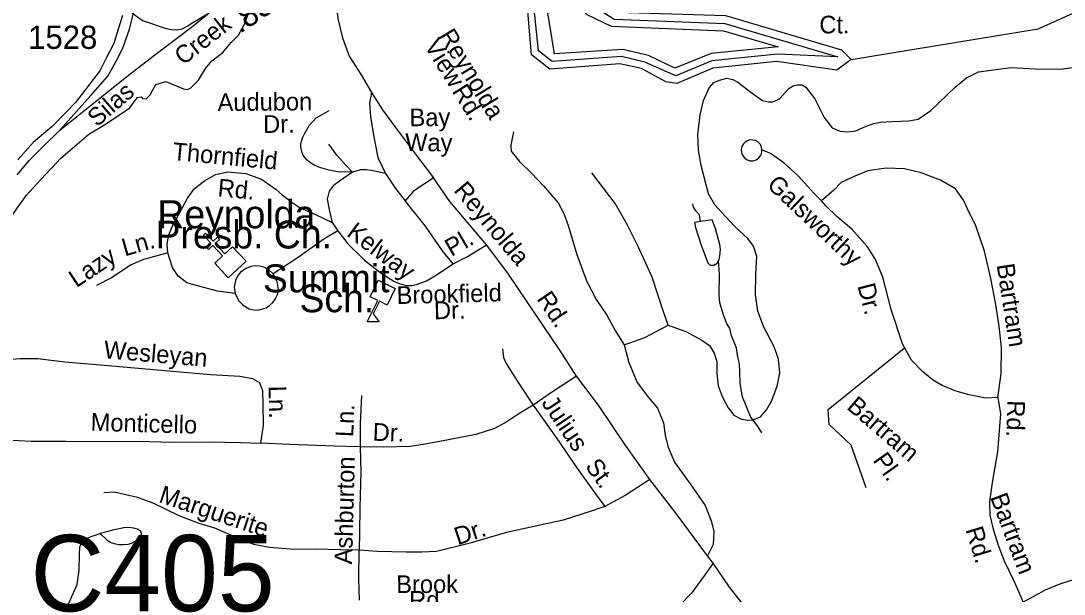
# Model space of a CAD drawing. Extents: x 1547597 to 1699558, y 810033 to 920809.
# Drawn here: x 1618156 to 1623759, y 864801 to 867878 of the extents above; entities that cross this region are included whole.
import ezdxf

# ---------------------------------------------------------------- set-up
doc = ezdxf.new("R2010")
doc.units = 0
for name, color, linetype in [('Exist Cultural Church CELL', 7, 'Continuous'), ('Exist Cultural Church Label', 7, 'Continuous'), ('Exist Cultural Educational Facility High CELL', 7, 'Continuous'), ('Exist Cultural Educational Facility High Label', 7, 'Continuous'), ('Exist Hydrographic Buffer Line', 7, 'Continuous'), ('Exist Hydrographic Creek Single Shore', 7, 'Continuous'), ('Exist Hydrographic Lake Shore', 7, 'Continuous'), ('Exist Hydrographic Misc Water Feature', 7, 'Continuous'), ('Exist Road Non-System Type 51', 7, 'Continuous'), ('Exist Road Non-System Type 51 Label', 7, 'Continuous'), ('Exist Road Primary Interstate Ramp 1 Lane Attributed', 7, 'Continuous'), ('Exist Road Primary NC Service Mileage Hundredths English Label', 7, 'Continuous'), ('Exist Road Primary NC UnDivided 4 Lane Attributed', 7, 'Continuous'), ('Exist Road Secondary Structure Culvert Number Label', 7, 'Continuous'), ('Exist Road Secondary Type 51 Divided Attributed', 7, 'Continuous'), ('Exist Road Secondary Type 51 Number Label', 7, 'Continuous')]:
    doc.layers.add(name, color=color, linetype=linetype)

msp = doc.modelspace()

# ---------------------------------------------------------------- linework, layer by layer
at = {"layer": 'Exist Cultural Church CELL'}
msp.add_lwpolyline([(1619197, 866577.5), (1619238.9, 866616.1), (1619187.4, 866672.2), (1619163.8, 866650.6), (1619153, 866662.3), (1619176.6, 866684), (1619135.9, 866728.3), (1619147.7, 866739.1), (1619188.4, 866694.8), (1619212, 866716.4), (1619222.8, 866704.7), (1619199.2, 866683), (1619250.7, 866626.9), (1619293.2, 866665.8), (1619365.2, 866587.4), (1619268.9, 866499.1)], close=True, dxfattribs=at)
at = {"layer": 'Exist Cultural Educational Facility High CELL'}
msp.add_lwpolyline([(1620165.6, 866440.8), (1620122.6, 866352.8), (1620081.2, 866373), (1620048.3, 866305.5), (1620080, 866263.1), (1620016.3, 866261.7), (1620072.6, 866377.2), (1620031.2, 866397.4), (1620074.2, 866485.4)], close=True, dxfattribs=at)
at = {"layer": 'Exist Hydrographic Buffer Line'}
for points in [[(1620900, 868064.4), (1621049.8, 868125.6), (1621176.8, 868246.5), (1621255.4, 868271.7), (1621206.7, 868118.1), (1621203.8, 867975), (1621342.4, 867886.6), (1621936.5, 867865), (1622544.4, 867686), (1622220.4, 867699.1), (1621867.7, 867663.6), (1621674.2, 867583.6), (1621507.9, 867657), (1621381.3, 867686.2), (1621009.2, 867659.6), (1620936.2, 867716.9), (1620900, 868064.4)], [(1621141.9, 868158.5), (1621163.8, 867975.3), (1621192.3, 867913.4), (1621326.1, 867850.1), (1621930.1, 867825.1), (1622223.3, 867738.8), (1621863.5, 867703.4), (1621668.7, 867624.6), (1621527, 867692.1), (1621389.8, 867725.3), (1621021.7, 867700.8), (1620968.8, 868032.4), (1621070.7, 868091.6), (1621141.9, 868158.5)]]:
    msp.add_lwpolyline(points, dxfattribs=at)
at = {"layer": 'Exist Hydrographic Creek Single Shore'}
for points in [[(1622614.8, 867671.1), (1623619.5, 867836.4), (1623807.3, 867920.2), (1624003, 868059.6), (1624501.8, 868216.3), (1624780.8, 868195), (1625278.3, 868121.2), (1625398.9, 868083.8), (1625565.9, 868096.9), (1625725.8, 868144.5), (1625814.8, 868197.1), (1625848.8, 868271.8), (1625880.2, 868588.2), (1626058.5, 868711.9), (1626152.5, 868851.2), (1626189.2, 869075.1), (1626361.8, 869229.8)], [(1618186.3, 866942), (1618264.7, 867028.3), (1618369.6, 867141), (1618520.5, 867269.2), (1618609.8, 867323.8), (1618740.9, 867411.7), (1618762.2, 867442.1), (1618782.7, 867466.2), (1618801.1, 867470.5), (1618808.2, 867462), (1618828.8, 867460.5), (1618838, 867468.3), (1618850, 867481.8), (1618879.8, 867536.4), (1618933.6, 867553.4), (1618986.8, 867530.7), (1619029.3, 867513), (1619049.9, 867510.1), (1619069, 867519.4), (1619109.4, 867559.8), (1619147.6, 867622.1), (1619181, 867663.9), (1619241.2, 867709.3), (1619285.8, 867761.7), (1619324.8, 867800.7), (1619357.4, 867860.2), (1619376.5, 867913.4)], [(1618074.1, 866786.6), (1618186.3, 866942)]]:
    msp.add_lwpolyline(points, dxfattribs=at)
at = {"layer": 'Exist Hydrographic Lake Shore'}
msp.add_line((1622614.8, 867671.1), (1622565.8, 867721.4), dxfattribs=at)
for points in [[(1622565.8, 867721.4), (1621942.8, 867904.8), (1621358.8, 867923.1), (1621243.8, 867974.7), (1621244.8, 868106), (1621305.8, 868298.5), (1621280.8, 868322), (1621155.8, 868281.8), (1621028.8, 868159.7), (1620868.7, 868061.1)], [(1621620.8, 867550.1), (1621488.8, 867621.8), (1621372.8, 867647.1), (1620996.8, 867618.6), (1620897.8, 867696.1), (1620868.7, 868061.1)], [(1622614.8, 867671.1), (1622538.8, 867613.6), (1622214.8, 867659.5), (1621871.8, 867623.9), (1621679.8, 867542.5), (1621620.8, 867550.1)]]:
    msp.add_lwpolyline(points, dxfattribs=at)
at = {"layer": 'Exist Hydrographic Misc Water Feature'}
for points in [[(1621806.9, 866800.5), (1621800.4, 866836.4), (1621780.7, 866858.6), (1621769, 866878.8), (1621764.9, 866896.7)], [(1621903.4, 866591.7), (1621905.6, 866595.6), (1621909.7, 866616.8), (1621914.1, 866650.6), (1621910.2, 866677.7), (1621887, 866761.1), (1621869.5, 866810.3), (1621806.9, 866800.5)], [(1621806.9, 866800.5), (1621774, 866795.3), (1621779.6, 866768.2), (1621809.6, 866674), (1621845.6, 866578.9), (1621857.8, 866567.5), (1621878.6, 866567.5), (1621894.9, 866576.8), (1621903.4, 866591.7)], [(1622136.3, 865665.9), (1622116.7, 865698.2), (1622075.5, 865754.7), (1622031, 865859.4), (1622019.9, 865931.5), (1622016.8, 865995.5), (1622015.4, 866035.5), (1622004, 866083.7), (1621998.6, 866123.7), (1621973.5, 866188.1), (1621964, 866228.2), (1621948.3, 866252.4), (1621929.1, 866300.7), (1621909.9, 866364.9), (1621906.5, 866404.9), (1621908.1, 866516.9), (1621903.4, 866591.7)]]:
    msp.add_lwpolyline(points, dxfattribs=at)
at = {"layer": 'Exist Road Non-System Type 51'}
for p, q in [((1620039.2, 867493), (1620098.2, 867400.3)), ((1619828.3, 866795.8), (1619857.6, 866751.2)), ((1622491.1, 865792.6), (1622899.6, 866121)), ((1622497.3, 865712.2), (1622491.1, 865792.6)), ((1622614.7, 865600.8), (1622497.3, 865712.2)), ((1622695.1, 865371.9), (1622614.7, 865600.8)), ((1621873.7, 864967.5), (1621844.5, 865005.9))]:
    msp.add_line(p, q, dxfattribs=at)
for points in [[(1619822.4, 868395.4), (1619824.2, 868236.4), (1619844.1, 868018.8), (1619858.6, 867891.7), (1619883.1, 867787.5), (1619919.9, 867689.4), (1619983.4, 867588.3), (1620039.2, 867493)], [(1621632.7, 866243.9), (1621728.1, 866210.3), (1621813.2, 866165), (1621854.6, 866136.3), (1621880, 866094), (1621893.1, 866049.7), (1621894.2, 865985.6), (1621901.1, 865919.6), (1621922.1, 865861.4), (1621955.1, 865800.9), (1621984.3, 865762.3), (1622025.9, 865739.6), (1622059.8, 865735.1), (1622089.8, 865736.7), (1622128, 865752), (1622160.6, 865789.5), (1622189.4, 865841), (1622218.6, 865916.4), (1622231.8, 865988.2), (1622224.9, 866062.2), (1622202.1, 866128.7), (1622146, 866233.5), (1622113.3, 866320), (1622100.9, 866408.1), (1622102.7, 866518.1), (1622108.2, 866613.8), (1622091.1, 866668.2), (1622060, 866710.7), (1621991, 866773.7), (1621918.4, 866850.8), (1621883.1, 866891.2), (1621848.4, 866949.3), (1621809.9, 867101.8), (1621795.6, 867183.9), (1621791.5, 867267.9), (1621804.4, 867373.7), (1621821.4, 867450.8), (1621851.8, 867519.2), (1621878, 867546.9), (1621908.1, 867560.7), (1621948.1, 867570.3), (1621980.4, 867563.4), (1622005.9, 867549.7), (1622083.4, 867490.9), (1622139, 867450.3), (1622170.9, 867444.1), (1622196.7, 867443.9), (1622230.8, 867459.4), (1622281.4, 867515.1), (1622303.9, 867530), (1622325.6, 867534.6), (1622352.2, 867534.4), (1622372.4, 867522.2), (1622420.7, 867459.6), (1622469.7, 867359.3), (1622513.2, 867304.8), (1622557.1, 867286.5), (1622595, 867282.2), (1622641, 867287.6), (1622695.3, 867313.1), (1622737.6, 867327.9), (1622773.2, 867333.8), (1622835.3, 867337.7), (1622925.4, 867340.9), (1622975.4, 867350.5), (1623043.8, 867397.7), (1623174.8, 867522.3), (1623235.3, 867571.7), (1623299.6, 867605.2), (1623475.5, 867627.5), (1623603.5, 867620.3), (1623741.3, 867618.9), (1623825.4, 867632.2)], [(1620039.2, 867493), (1620028.3, 867436.7), (1620033.6, 867364.6), (1620050.6, 867264.6), (1620073.4, 867144.5), (1620114.7, 867058)], [(1619936.9, 867065.8), (1619856.9, 867068.4), (1619810.3, 867076.8), (1619761.1, 867091.4), (1619733.9, 867101.9), (1619711.4, 867115.8), (1619693.3, 867130.6), (1619673.8, 867154.2), (1619664.6, 867174.4), (1619660.3, 867200.3), (1619660, 867216.3), (1619662.5, 867232.2), (1619670.4, 867254.7), (1619679, 867272.1), (1619705.3, 867317.8), (1619741.7, 867357.5), (1619812, 867396.7)], [(1620098.2, 867400.3), (1620167.1, 867305.7), (1620275.3, 867162.4), (1620371.9, 867035.3)], [(1620802.2, 867283.3), (1620787.6, 867211.4), (1620789.3, 867179.5), (1620832.8, 867125), (1620898.2, 867060.5), (1620963.4, 866991.9), (1621042.1, 866901.8), (1621071.2, 866844.8), (1621096.1, 866780.3), (1621139.6, 866629.7), (1621193.1, 866482.9), (1621245.3, 866382.2), (1621303.8, 866299.2), (1621348.6, 866216.4), (1621395.3, 866139.8)], [(1619936.9, 867065.8), (1619899.3, 867106.2), (1619853.7, 867156.5), (1619810.3, 867216.8)], [(1622136.4, 867186.6), (1622134.3, 867200.1), (1622127.8, 867214.2), (1622117.4, 867226), (1622100.8, 867235.8), (1622087.7, 867238.6), (1622076.9, 867238.8), (1622066.2, 867237.1), (1622055.1, 867232.7), (1622045.6, 867226.7), (1622036.4, 867217.7), (1622028.9, 867204.4), (1622024.8, 867186.1), (1622028.5, 867162.2), (1622039.9, 867144.3), (1622055.9, 867133), (1622072.6, 867127.7), (1622088.8, 867127.7), (1622104.3, 867132.2), (1622119.9, 867142.7), (1622131.5, 867158.9), (1622136, 867174), (1622136.4, 867186.6)], [(1622455.6, 866911.6), (1622414.1, 866954), (1622330.9, 867046.8), (1622253.6, 867115.4), (1622182.2, 867166.1), (1622136.4, 867186.6)], [(1618944.7, 866632.2), (1618941.5, 866678.3), (1618948.2, 866726), (1618971.2, 866781.7), (1619012.2, 866853), (1619050.2, 866927.3), (1619088.7, 866977.9), (1619142.9, 867019.5), (1619201.2, 867052.9), (1619267.4, 867068.2), (1619363.3, 867059.2), (1619448.9, 867028.5), (1619526.2, 866973.7), (1619559.6, 866945), (1619613.2, 866902.8), (1619655.8, 866874.5), (1619741.1, 866837.2), (1619828.3, 866795.8)], [(1619936.9, 867065.8), (1619866.5, 867018.4), (1619833.2, 866992.4), (1619811.4, 866963.6), (1619801.4, 866921.1), (1619813.3, 866855.9), (1619828.3, 866795.8)], [(1620114.7, 867058), (1620036.8, 867074.8), (1620010.8, 867078.5), (1619980.8, 867078.1), (1619936.9, 867065.8)], [(1620114.7, 867058), (1620167.9, 866977.6), (1620219.2, 866912.4)], [(1620371.9, 867035.3), (1620263.6, 866962.7), (1620219.2, 866912.4)], [(1620657.3, 866676.3), (1620460.4, 866909.3), (1620371.9, 867035.3)], [(1621632.7, 866243.9), (1621604.1, 866326.3), (1621547.1, 866503.1), (1621471.8, 866666.2), (1621411.7, 866785.3), (1621347.8, 866898), (1621222, 867063.3)], [(1623402.4, 865857.2), (1623420.3, 865982.7), (1623422.6, 866124.7), (1623410.5, 866238.8), (1623392.5, 866355), (1623364.9, 866495.3), (1623331.3, 866641.8), (1623285.6, 866778.4), (1623239.3, 866873.6), (1623219.2, 866916.3), (1623175.8, 866976.6), (1623094.3, 867023.5), (1622990.6, 867062.4), (1622901, 867083.2), (1622803, 867088.2), (1622705, 867073), (1622634.8, 867043.8), (1622562.5, 867010.5), (1622522.2, 866968.8), (1622455.6, 866911.6)], [(1620477.9, 866573.3), (1620421.2, 866644.1), (1620329.4, 866775.9), (1620219.2, 866912.4)], [(1623402.4, 865857.2), (1623336.3, 865852.1), (1623240.8, 865871.7), (1623173.2, 865892.8), (1623103.7, 865919.9), (1623052.3, 865950.7), (1622999, 865995.6), (1622940.2, 866056.5), (1622891.6, 866145.3), (1622830.6, 866328.2), (1622785.6, 866502.8), (1622745.3, 866597.5), (1622702.4, 866666), (1622618.1, 866759.4), (1622539.2, 866828.6), (1622481.3, 866883.4), (1622455.6, 866911.6)], [(1619857.6, 866751.2), (1619782.9, 866706.4), (1619639.3, 866604.9), (1619510.2, 866521.1)], [(1619857.6, 866751.2), (1619912.4, 866680.4), (1620000.9, 866593), (1620091.5, 866523.5), (1620158.7, 866480.5), (1620182.9, 866470.2), (1620205.6, 866462.9), (1620230.9, 866458.2), (1620255.9, 866457.7), (1620281, 866462.8), (1620334, 866483.3), (1620388.9, 866515), (1620477.9, 866573.3)], [(1620477.9, 866573.3), (1620554.4, 866613.9), (1620657.3, 866676.3)], [(1621139.3, 865970.9), (1621049.7, 866110.2), (1620922.8, 866298.1), (1620770.7, 866524.5), (1620657.3, 866676.3)], [(1618944.7, 866632.2), (1618880.5, 866615.3), (1618814.3, 866596.4), (1618747.9, 866569.4), (1618642.9, 866499.2), (1618562.2, 866458.5)], [(1619306.7, 866414.3), (1619211.1, 866426.9), (1619111.6, 866453.5), (1619047.9, 866472.6), (1619000.6, 866507.4), (1618969.3, 866553.9), (1618944.7, 866632.2)], [(1619510.2, 866521.1), (1619488.2, 866541.3), (1619460.4, 866555.7), (1619438.9, 866561.1), (1619415, 866562.4), (1619391.1, 866559.3), (1619366.3, 866549.6), (1619336.2, 866528.4), (1619318.8, 866508.1), (1619307.7, 866484.6), (1619301.8, 866449.5), (1619306.7, 866414.3)], [(1619306.7, 866414.3), (1619324.1, 866376.4), (1619349, 866351.4), (1619381.1, 866332.8), (1619406.2, 866327.1), (1619428.4, 866326), (1619448.3, 866330.4), (1619472.4, 866337.9), (1619491.7, 866350.1), (1619509.8, 866366.4), (1619521, 866383.6), (1619535.2, 866412.1), (1619539.1, 866435.6), (1619532.5, 866478.4), (1619510.2, 866521.1)], [(1621395.3, 866139.8), (1621507.7, 866178), (1621632.7, 866243.9)], [(1621395.3, 866139.8), (1621421.5, 866043.4), (1621465.8, 865936.7), (1621526.4, 865855.8), (1621575.4, 865799), (1621608.1, 865720.5), (1621616.9, 865652.5), (1621631.8, 865590.1), (1621666.4, 865509.8), (1621750.5, 865392.4), (1621830.4, 865277.1), (1621863.1, 865194.6), (1621878.2, 865138.5), (1621874.9, 865066.5), (1621844.5, 865005.9)], [(1620742, 866117.3), (1620747.3, 866071.1), (1620762.9, 866039), (1620830.9, 865932), (1620907, 865814.7)], [(1619445.3, 865610.7), (1619458.8, 865706.5), (1619456.7, 865818.4), (1619455.8, 865892.2), (1619438.6, 865934.6), (1619401.1, 865957.2), (1619331.3, 865968.2), (1619175.6, 865978.8), (1618928.3, 865998.8), (1618625.1, 866025.7), (1618391.5, 866045.5), (1618246, 866063.9), (1618152.2, 866063.4), (1618088.2, 866058.4), (1618057.8, 866037.1), (1617998.3, 865938), (1617916, 865795.4), (1617858.3, 865682.5)], [(1621139.3, 865970.9), (1621011.9, 865886.9), (1620907, 865814.7)], [(1621533.7, 865416.8), (1621400.8, 865602.8), (1621258.6, 865815), (1621139.3, 865970.9)], [(1619984.8, 865867.7), (1619978.3, 865715.9), (1619978.4, 865592.1)], [(1623402.4, 865857.2), (1623416.8, 865768.8), (1623401.5, 865565.2), (1623372.7, 865399.7), (1623359.2, 865296.1), (1623359.9, 865224.1), (1623378.6, 865149.9), (1623403.2, 865069.5), (1623435.9, 864983), (1623489.9, 864872.2), (1623538.4, 864758.4)], [(1620907, 865814.7), (1620836.3, 865772), (1620765.5, 865725.2), (1620699.2, 865690.1), (1620598.7, 865657.9), (1620452.4, 865628.3), (1620328.1, 865606.2), (1620246, 865593.6), (1620102.2, 865589.9), (1619978.4, 865592.1)], [(1620907, 865814.7), (1620973.3, 865721.7), (1621047.5, 865618.6), (1621133.4, 865491.2), (1621236.9, 865345.6), (1621291.6, 865270.8)], [(1617858.3, 865682.5), (1617915.8, 865659.5), (1617993.4, 865636.3), (1618107.1, 865626.4), (1618210.9, 865622.7), (1618396.5, 865621.8), (1618608.4, 865620.3), (1618788.1, 865621.4), (1618965.9, 865616.4), (1619165.7, 865619.2), (1619337.5, 865614.5), (1619445.3, 865610.7)], [(1619978.4, 865592.1), (1619840.6, 865594.3), (1619601, 865604.1), (1619445.3, 865610.7)], [(1619978.4, 865592.1), (1619982.1, 865457.9), (1619977, 865266.1), (1619974.7, 865132.3), (1619972.6, 865036.9)], [(1621533.7, 865416.8), (1621402.3, 865330.8), (1621291.6, 865270.8)], [(1621844.5, 865005.9), (1621670.6, 865240.5), (1621533.7, 865416.8)], [(1619972.6, 865036.9), (1619874.5, 865039.4), (1619740.7, 865041.5), (1619625.8, 865040.6), (1619491.3, 865051.9), (1619406.2, 865067.6), (1619283.2, 865117.5), (1619197.9, 865155), (1619112.6, 865180.4), (1619005.8, 865221.3), (1618867.2, 865288.6), (1618783, 865320), (1618657.3, 865348.1), (1618601.8, 865344.1)], [(1621291.6, 865270.8), (1621219.6, 865247), (1621068.9, 865197.4), (1620764, 865132), (1620562.3, 865073.4), (1620387.7, 865030.1), (1620308.6, 865025.9), (1620224.7, 865025.2), (1620071.6, 865029.4), (1619972.6, 865036.9)], [(1618582.2, 865126.9), (1618619.7, 865090.3), (1618638.7, 865078.7), (1618657.3, 865071.8), (1618682.3, 865067.2), (1618707.1, 865066.9), (1618732.1, 865068.6), (1618751.2, 865074.3), (1618788.9, 865095.9), (1618800.5, 865108.3), (1618804, 865118.6), (1618804.2, 865129.6), (1618798.2, 865139.5), (1618782.4, 865148.7), (1618760.5, 865154.1), (1618737.1, 865158.2), (1618708.7, 865157), (1618650.4, 865143.9), (1618582.2, 865126.9)], [(1618412.2, 864747.9), (1618439.1, 864807.4), (1618457.8, 864853.1), (1618469.1, 864928.9), (1618470.5, 865014.9), (1618473.1, 865054.9), (1618479.4, 865071.4), (1618489.7, 865084.6), (1618506.6, 865097.2), (1618528, 865107.8), (1618582.2, 865126.9)], [(1619974.7, 864768.5), (1619970.6, 864882.4), (1619972.6, 865036.9)], [(1624620.7, 865036.2), (1624520.4, 865013.8), (1624387.1, 864988), (1624207, 864957), (1624014.7, 864930.1), (1623874.3, 864898), (1623740.6, 864856.7), (1623658, 864822.6), (1623538.4, 864758.4)], [(1621873.7, 864967.5), (1621826.7, 864898.2), (1621757.2, 864805.5), (1621692.2, 864738.6), (1621633.5, 864695.6), (1621505, 864643.6), (1621348.4, 864598.3), (1621219.7, 864548.3), (1621142.8, 864495.6), (1621102, 864440.4), (1621084.4, 864401), (1621077, 864359.5), (1621081.7, 864304.8), (1621094.6, 864230.7), (1621115.5, 864166.2), (1621148.1, 864132.7), (1621171.3, 864119.5)], [(1622537.2, 864104.5), (1622462.5, 864200.3), (1622284, 864409), (1622108.3, 864651.7), (1621961.6, 864838), (1621873.7, 864967.5)]]:
    msp.add_lwpolyline(points, dxfattribs=at)
at = {"layer": 'Exist Road Primary Interstate Ramp 1 Lane Attributed'}
msp.add_lwpolyline([(1618750.8, 867924.1), (1618769.8, 867909.6), (1618808.7, 867880.6), (1618936.8, 867836.9), (1618964.9, 867831.5), (1618989.4, 867829.7), (1619019.3, 867834.2), (1619049.3, 867849.6), (1619079.2, 867868.7), (1619100.1, 867882.3), (1619167.2, 867921.7)], dxfattribs=at)
at = {"layer": 'Exist Road Primary NC UnDivided 4 Lane Attributed'}
for points in [[(1618701.2, 867907), (1618670, 867805.6), (1618654.4, 867756.8), (1618614.1, 867677.4), (1618579.3, 867609.4), (1618449, 867439.4), (1618332.8, 867319.9), (1618323.7, 867310.4), (1618221.9, 867224.6), (1618138.6, 867131.7)], [(1618365.3, 867291.9), (1618733.8, 867587.4), (1618904.6, 867717.8), (1619072.5, 867843.9), (1619167.2, 867921.7)], [(1618135, 867052.4), (1618200.9, 867128.2), (1618301.7, 867231.3), (1618337, 867263), (1618365.3, 867291.9)]]:
    msp.add_lwpolyline(points, dxfattribs=at)
at = {"layer": 'Exist Road Secondary Type 51 Divided Attributed'}
msp.add_lwpolyline([(1618365.3, 867291.9), (1618529.6, 867475.5), (1618623.3, 867581.7), (1618667.9, 867661.8), (1618703.3, 867731.9), (1618738.8, 867833.3), (1618765.7, 867940.3)], dxfattribs=at)

# ---------------------------------------------------------------- texts
at = {"layer": 'Exist Cultural Church Label'}
for s, p in [('Reynolda', (1618889.2, 866764.9)), ('Presb. Ch.', (1618879.2, 866656.3))]:
    msp.add_text(s, height=150, dxfattribs=at).set_placement(p)
at = {"layer": 'Exist Cultural Educational Facility High Label'}
for s, p in [('Summit', (1619456, 866421)), ('Sch.', (1619652.3, 866314))]:
    msp.add_text(s, height=150, dxfattribs=at).set_placement(p)
at = {"layer": 'Exist Road Non-System Type 51 Label'}
for s, rotation, p in [('Creek', 37.8892, (1619027.3, 867636.5)), ('Ct.', 359.9114, (1622444.3, 867811)), ('Reynolda', 301.3483, (1620397.7, 867799.3)), ('View', 301.6782, (1620319.6, 867745.3)), ('Rd.', 302.2349, (1620468.4, 867500.3)), ('Silas', 40.866, (1618564.6, 867305.5)), ('Audubon', 0.5149, (1619212.4, 867394)), ('Dr.', 0.7319, (1619457.5, 867276.6)), ('Bay', 0.384, (1620243.5, 867312.5)), ('Way', 359.231, (1620219.2, 867180.1)), ('Thornfield', 354.6667, (1618967.3, 867131.8)), ('Galsworthy', 316.5964, (1622157.3, 866991.3)), ('Rd.', 354.6667, (1619210, 866936.8)), ('Reynolda', 310.2032, (1620476.7, 866966.3)), ('Kelway', 322.9369, (1619900.1, 866728.1)), ('Ln.', 15.9045, (1618713.7, 866613.3)), ('Pl.', 30.0201, (1620468.5, 866610.3)), ('Lazy', 33.7111, (1618454.1, 866443)), ('Bartram', 278.7779, (1623396.5, 866568.8)), ('Brookfield', 1.4695, (1620175, 866357.9)), ('Rd.', 304.0284, (1620922.9, 866385.9)), ('Dr.', 284.4777, (1622648.5, 866456.7)), ('Dr.', 1.4695, (1620375.7, 866276.1)), ('Wesleyan', 355.1713, (1618598.3, 866067.7)), ('Ln.', 271.1558, (1619486, 865918.8)), ('Julius', 303.9754, (1620948.6, 865826.8)), ('Bartram', 319.3913, (1622586.3, 865799)), ('Ln.', 87.5551, (1619940.4, 865642.6)), ('Rd.', 268.3264, (1623454.5, 865842.5)), ('Monticello', 358.387, (1618529.6, 865677.9)), ('Dr.', 357.6423, (1620043.9, 865624.9)), ('Ashburton', 88.4793, (1619934.5, 864959.7)), ('St.', 305.4118, (1621183.3, 865486.3)), ('Pl.', 305.291, (1622729, 865519.3)), ('Marguerite', 341.6635, (1618891.1, 865295.9)), ('Bartram', 290.6836, (1623360.5, 865321.9)), ('Dr.', 18.2105, (1620502.1, 865062.8)), ('Rd.', 287.0149, (1623228.6, 865147.4)), ('Brook', 0.1629, (1620172, 864806.6)), ('Rd.', 0.1629, (1620241.7, 864721.9))]:
    msp.add_text(s, height=95, rotation=rotation, dxfattribs=at).set_placement(p)
at = {"layer": 'Exist Road Primary NC Service Mileage Hundredths English Label'}
msp.add_text('.83', height=125, rotation=34.1377, dxfattribs=at).set_placement((1619332.5, 867807.3))
at = {"layer": 'Exist Road Secondary Structure Culvert Number Label'}
msp.add_text('C405', height=410.1, dxfattribs=at).set_placement((1618207.7, 864708.5))
at = {"layer": 'Exist Road Secondary Type 51 Number Label'}
msp.add_text('1528', height=125, dxfattribs=at).set_placement((1618194.6, 867727.8))

doc.saveas('drawing.dxf')
